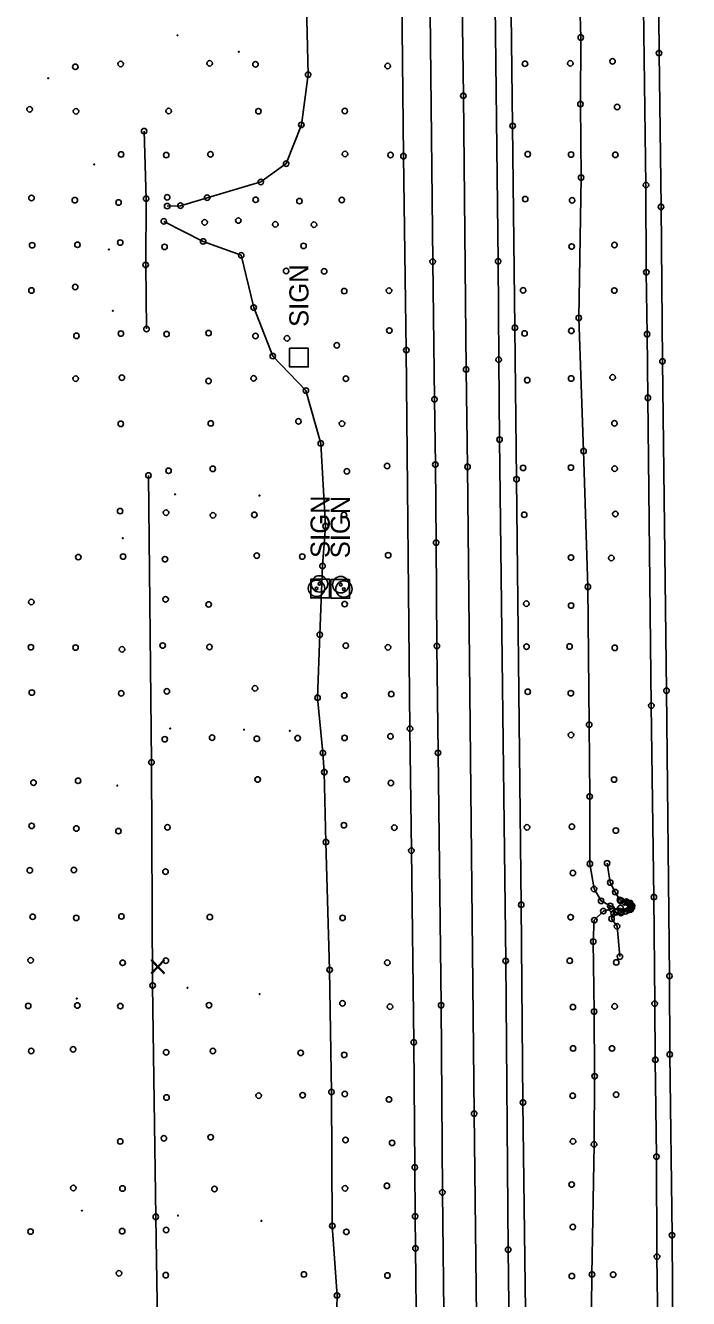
# Model space of a CAD drawing. Extents: x 20503438 to 20508873, y 7964251 to 7984667.
# Drawn here: x 20505218.1 to 20505460.6, y 7983269.7 to 7983735.5 of the extents above; entities that cross this region are included whole.
import ezdxf

# ---------------------------------------------------------------- set-up
doc = ezdxf.new("R2010")
doc.units = 0
for name, color, linetype in [('SurBreakLine', 7, 'Continuous'), ('SurConcreteSlab', 7, 'Continuous'), ('SurControl', 7, 'Continuous'), ('SurDrainageArrowDown', 7, 'Continuous'), ('SurDrainageArrowUp', 7, 'Continuous'), ('SurEdgeRoadPaved', 7, 'Continuous'), ('SurEdgeShoulderPaved', 7, 'Continuous'), ('SurFenceWire', 7, 'Continuous'), ('SurPointsNonDTM', 7, 'Continuous'), ('SurRoadPoints', 7, 'Continuous'), ('SurSurveyPoints', 7, 'Continuous')]:
    doc.layers.add(name, color=color, linetype=linetype)

msp = doc.modelspace()

# ---------------------------------------------------------------- linework, layer by layer
at = {"layer": 'SurBreakLine'}
for points in [[(20505388.09, 7982786.72), (20505387.46, 7982826.69), (20505386.97, 7982893.61), (20505385.8, 7982999.79), (20505385.32, 7983030.07), (20505384.98, 7983076.27), (20505384.47, 7983119.49), (20505384.1, 7983167.57), (20505382.15, 7983337.32), (20505379.76, 7983573.99), (20505379.24, 7983609.63), (20505378.24, 7983709.76), (20505377.29, 7983778.59), (20505376.87, 7983823.71), (20505376.2, 7983914.92), (20505375.66, 7983955.45), (20505374.47, 7984054.03), (20505371.04, 7984409.5), (20505370.34, 7984465.16)], [(20505430.81, 7983428.95), (20505431.94, 7983421.89), (20505433.78, 7983418.39), (20505435.46, 7983415.54), (20505437.89, 7983414.91), (20505439.2, 7983414.35), (20505439.89, 7983413.53), (20505439.86, 7983412.7), (20505439.4, 7983412.02), (20505437.62, 7983411.33), (20505436.03, 7983410.93), (20505435.76, 7983410.73), (20505434.14, 7983411.03), (20505433.19, 7983410.64), (20505432.43, 7983408.64), (20505434.42, 7983405.87), (20505435.48, 7983394.78)]]:
    msp.add_lwpolyline(points, dxfattribs=at)
at = {"layer": 'SurConcreteSlab'}
msp.add_lwpolyline([(20505435.85, 7983415.35), (20505438.25, 7983414.57), (20505439.21, 7983414.26), (20505439.53, 7983413.73), (20505439.61, 7983412.57), (20505439.09, 7983412.1), (20505438.55, 7983411.79), (20505435.96, 7983411), (20505435.9, 7983411.25), (20505438.99, 7983412.12), (20505438.94, 7983414.02), (20505437.2, 7983414.63), (20505435.64, 7983415.19)], dxfattribs=at)
at = {"layer": 'SurControl'}
msp.add_lwpolyline([(20505268.93, 7983393.31), (20505268.67, 7983393.56), (20505266.53, 7983391.34), (20505264.39, 7983393.56), (20505264.13, 7983393.31), (20505266.28, 7983391.08), (20505264.13, 7983388.85), (20505264.39, 7983388.6), (20505266.53, 7983390.82), (20505268.67, 7983388.6), (20505268.93, 7983388.85), (20505266.78, 7983391.08)], close=True, dxfattribs=at)
for centre in [(20505273.7, 7983731.89), (20505296.12, 7983725.88), (20505226.42, 7983716.17), (20505243.27, 7983684.65), (20505248.61, 7983653.5), (20505250.04, 7983631.09), (20505272.81, 7983563.94), (20505303.65, 7983563.47), (20505253.69, 7983547.89), (20505271.04, 7983478.26), (20505298.03, 7983477.81), (20505314.75, 7983477.39), (20505251.69, 7983457.37), (20505236.87, 7983379.43), (20505277.36, 7983383.39), (20505303.75, 7983381.07), (20505238.75, 7983301.84), (20505273.87, 7983300.04), (20505304.38, 7983298.09)]:
    msp.add_circle(centre, 0.15, dxfattribs=at)
at = {"layer": 'SurDrainageArrowDown'}
msp.add_lwpolyline([(20505331.52, 7983247.58), (20505332.03, 7983270.82), (20505330.3, 7983296.26), (20505330, 7983345.23), (20505329.34, 7983389.92), (20505327.98, 7983436.68), (20505327.39, 7983462.27), (20505326.88, 7983469.31), (20505324.92, 7983489.49), (20505325.74, 7983512.6), (20505326.72, 7983537.72), (20505327.84, 7983552.32), (20505326.1, 7983582.56), (20505320.66, 7983601.9), (20505308.53, 7983614.51), (20505301.56, 7983632.27), (20505297, 7983651.4), (20505283.09, 7983656.45), (20505268.69, 7983663.8)], dxfattribs=at)
at = {"layer": 'SurDrainageArrowUp'}
for points in [[(20505269.92, 7983669.38), (20505274.77, 7983669.53), (20505284.53, 7983672.48), (20505304.14, 7983678.22), (20505313.43, 7983684.93), (20505319, 7983699.12), (20505321.46, 7983717.49), (20505321, 7983737.68), (20505321.32, 7983758.43), (20505323.53, 7983782.34), (20505317.99, 7983807.64), (20505321.24, 7983834.42), (20505321.13, 7983884.66), (20505321.58, 7983916.57), (20505320.13, 7983948.66), (20505320.6, 7983976.69), (20505320.82, 7984005.51), (20505319.96, 7984030.22), (20505318.49, 7984055.46), (20505317.7, 7984079.41), (20505317.25, 7984104.99), (20505316.36, 7984122.1)], [(20505431.94, 7983413.35), (20505428.59, 7983415.16), (20505426.01, 7983419.53), (20505424.51, 7983428.73), (20505424.44, 7983453.4), (20505424.24, 7983479.66), (20505423.78, 7983530.09), (20505422.18, 7983579.75), (20505420.43, 7983628.49), (20505421.29, 7983679.84), (20505421.05, 7983706.71), (20505421.16, 7983731.09), (20505419.67, 7983779.95)], [(20505435.69, 7983412.57), (20505432.5, 7983412.27), (20505429.44, 7983411.43), (20505426.11, 7983408.1), (20505425.72, 7983400.28), (20505426.05, 7983374.69), (20505426.24, 7983351.03), (20505426.02, 7983326.08), (20505425.25, 7983278.5), (20505424.77, 7983230.05), (20505424.95, 7983179.92)]]:
    msp.add_lwpolyline(points, dxfattribs=at)
at = {"layer": 'SurEdgeRoadPaved'}
for points in [[(20505403.63, 7982474.93), (20505402.88, 7982536.9), (20505402.67, 7982576.67), (20505401.63, 7982665.51), (20505399.87, 7982796.43), (20505397.64, 7982996.42), (20505397.31, 7983043.62), (20505395.75, 7983196.59), (20505394.62, 7983287.56), (20505393.71, 7983393.22), (20505391.47, 7983583.96), (20505391.16, 7983613.2), (20505390.95, 7983649.19), (20505388.69, 7983846.62), (20505387.86, 7983937.63), (20505387.13, 7984000.04), (20505387.09, 7984002.85), (20505386.65, 7984030.88), (20505382.6, 7984465.04)], [(20505460.57, 7982745.92), (20505460.02, 7982819.87), (20505458.85, 7982918.92), (20505458.72, 7982952.55), (20505457.28, 7983055.18), (20505456.07, 7983138.84), (20505455.85, 7983167.22), (20505455.42, 7983198.13), (20505455.22, 7983224.45), (20505454.85, 7983254.02), (20505454.55, 7983292.83), (20505453.72, 7983358.98), (20505453.59, 7983387.67), (20505452.51, 7983492.09), (20505451.03, 7983612.62), (20505450.51, 7983669.13), (20505449.78, 7983725.38), (20505449.64, 7983752.99)], [(20505376.87, 7982720.03), (20505375.97, 7982814.93), (20505375.18, 7982868.35), (20505374.84, 7982896.8), (20505373.9, 7983003.41), (20505373.63, 7983032.61), (20505373.23, 7983073.5), (20505372.9, 7983110.52), (20505372.72, 7983130.62), (20505372.2, 7983185.46), (20505371.76, 7983214.03), (20505371.18, 7983254.01), (20505370.55, 7983308.55), (20505370.11, 7983376.99), (20505368.96, 7983469.33), (20505368.55, 7983508.46), (20505368.26, 7983546.26), (20505367.99, 7983574.82), (20505367.67, 7983598.7), (20505367.02, 7983649.08), (20505365.92, 7983751.56)]]:
    msp.add_lwpolyline(points, dxfattribs=at)
at = {"layer": 'SurEdgeShoulderPaved'}
for points in [[(20505366.98, 7982718.13), (20505365.41, 7982861.87), (20505365.07, 7982881.72), (20505364.41, 7982928.72), (20505364.19, 7982960.53), (20505363.22, 7983054.03), (20505362.96, 7983074.76), (20505362.61, 7983110.31), (20505362.42, 7983145.46), (20505361.97, 7983183.06), (20505361.41, 7983217.22), (20505361.15, 7983254.72), (20505360.71, 7983288.06), (20505360.6, 7983299.77), (20505360.47, 7983317.66), (20505360.11, 7983363.4), (20505359.23, 7983433.57), (20505358.71, 7983478.18), (20505357.37, 7983616.7), (20505356.33, 7983687.67), (20505355.63, 7983757.41)], [(20505406.44, 7982753), (20505405.66, 7982815.99), (20505404.36, 7982949.58), (20505403.42, 7983021.17), (20505402.75, 7983090.32), (20505402.21, 7983129.29), (20505402.08, 7983165.66), (20505401.47, 7983227.06), (20505400.04, 7983341.4), (20505399.38, 7983413.75), (20505397.66, 7983569.46), (20505397.07, 7983624.87), (20505396.26, 7983698.73), (20505395.49, 7983760.73)], [(20505454.87, 7982799.91), (20505454.43, 7982834.05), (20505454.19, 7982863.65), (20505453.63, 7982922.83), (20505451.09, 7983092.97), (20505450.78, 7983121.42), (20505450.67, 7983149.63), (20505450.35, 7983185.44), (20505449.91, 7983215.31), (20505449.29, 7983259.23), (20505449.04, 7983285.01), (20505448.83, 7983321.6), (20505448.42, 7983357.03), (20505448.19, 7983377.57), (20505447.91, 7983416.56), (20505446.96, 7983486.61), (20505445.72, 7983599.24), (20505445.42, 7983622.54), (20505445.14, 7983645.21), (20505445.01, 7983677.11), (20505444.05, 7983741.95)]]:
    msp.add_lwpolyline(points, dxfattribs=at)
at = {"layer": 'SurFenceWire'}
for points in [[(20505262.37, 7983624.43), (20505262.08, 7983647.88), (20505262.23, 7983672.11), (20505261.49, 7983696.84)], [(20505263.07, 7983570.84), (20505264.2, 7983465.89), (20505264.6, 7983384.22), (20505265.76, 7983299.57), (20505267.13, 7983213.61), (20505277.91, 7983026.79), (20505279.9, 7982903.03), (20505280.94, 7982831.19), (20505284.45, 7982664.16), (20505302.4, 7982645.24), (20505317.11, 7982628.42), (20505340.63, 7982610.34)]]:
    msp.add_lwpolyline(points, dxfattribs=at)
at = {"layer": 'SurPointsNonDTM'}
for centre in [(20505261.49, 7983696.84), (20505262.23, 7983672.11), (20505262.08, 7983647.88), (20505262.37, 7983624.43), (20505263.07, 7983570.84), (20505264.2, 7983465.89), (20505264.6, 7983384.22), (20505265.76, 7983299.57)]:
    msp.add_circle(centre, 1, dxfattribs=at)
at = {"layer": 'SurRoadPoints'}
for points in [[(20505321.53, 7983613.98), (20505321.53, 7983613.98), (20505321.53, 7983617.41), (20505314.67, 7983617.41), (20505314.67, 7983610.55), (20505321.53, 7983610.55), (20505321.53, 7983613.98)], [(20505329.29, 7983529.45), (20505329.29, 7983529.45), (20505329.29, 7983532.88), (20505322.43, 7983532.88), (20505322.43, 7983526.02), (20505329.29, 7983526.02), (20505329.29, 7983529.45)], [(20505336.65, 7983529.32), (20505336.65, 7983529.32), (20505336.65, 7983532.75), (20505329.79, 7983532.75), (20505329.79, 7983525.89), (20505336.65, 7983525.89), (20505336.65, 7983529.32)]]:
    msp.add_lwpolyline(points, dxfattribs=at)
for centre, radius in [((20505325.63, 7983531.17), 3), ((20505333.39, 7983530.88), 3), ((20505324.54, 7983529.51), 3), ((20505324.54, 7983529.51), 0.5), ((20505325.63, 7983531.17), 0.5), ((20505334.55, 7983529.28), 3), ((20505333.39, 7983530.88), 0.5), ((20505334.55, 7983529.28), 0.5)]:
    msp.add_circle(centre, radius, dxfattribs=at)
at = {"layer": 'SurSurveyPoints'}
for centre in [(20505421.16, 7983731.09), (20505449.78, 7983725.38), (20505236.34, 7983720.37), (20505252.92, 7983721.41), (20505285.46, 7983721.62), (20505302.22, 7983721.27), (20505350.55, 7983720.65), (20505400.75, 7983721.47), (20505417.35, 7983721.62), (20505432.8, 7983722.37), (20505321.46, 7983717.49), (20505378.24, 7983709.76), (20505219.65, 7983704.81), (20505236.59, 7983704.08), (20505270.47, 7983704.19), (20505303.31, 7983704.11), (20505334.87, 7983704.17), (20505421.05, 7983706.71), (20505434.47, 7983705.65), (20505319, 7983699.12), (20505396.26, 7983698.73), (20505253.08, 7983688.3), (20505269.59, 7983688.06), (20505285.74, 7983688.33), (20505334.97, 7983688.45), (20505351.62, 7983688.09), (20505356.33, 7983687.67), (20505401.78, 7983688.4), (20505417.63, 7983688.26), (20505433.81, 7983688.16), (20505313.43, 7983684.93), (20505304.14, 7983678.22), (20505421.29, 7983679.84), (20505445.01, 7983677.11), (20505220.32, 7983672.38), (20505236.16, 7983671.56), (20505269.94, 7983672.58), (20505284.53, 7983672.48), (20505302.28, 7983671.7), (20505333.78, 7983671.64), (20505400.86, 7983671.95), (20505418, 7983671.49), (20505252.16, 7983670.71), (20505269.92, 7983669.38), (20505274.77, 7983669.53), (20505318.29, 7983671.21), (20505450.51, 7983669.13), (20505268.69, 7983663.8), (20505283.62, 7983663.47), (20505295.95, 7983664.09), (20505309.47, 7983662.72), (20505323.6, 7983662.59), (20505220.56, 7983655.07), (20505237.12, 7983655.24), (20505252.75, 7983656.06), (20505268.97, 7983654.47), (20505283.09, 7983656.45), (20505319.8, 7983654.85), (20505417.82, 7983654.6), (20505433.49, 7983655.17), (20505297, 7983651.4), (20505367.02, 7983649.08), (20505390.95, 7983649.19), (20505313.41, 7983645.63), (20505327.33, 7983645.52), (20505445.14, 7983645.21), (20505236.3, 7983639.77), (20505220.29, 7983638.52), (20505334.67, 7983638.3), (20505351.06, 7983638.46), (20505400.07, 7983638.57), (20505433.44, 7983638.5), (20505301.56, 7983632.27), (20505397.07, 7983624.87), (20505420.43, 7983628.49), (20505236.76, 7983621.92), (20505253.01, 7983622.77), (20505269.69, 7983622.56), (20505285.05, 7983622.93), (20505302.23, 7983621.86), (20505313.76, 7983620.99), (20505351.15, 7983623.87), (20505400.61, 7983622.8), (20505417.74, 7983623.76), (20505445.42, 7983622.54), (20505331.95, 7983618.47), (20505357.37, 7983616.7), (20505308.53, 7983614.51), (20505391.16, 7983613.2), (20505451.03, 7983612.62), (20505236.47, 7983606.26), (20505253.38, 7983606.64), (20505301.53, 7983606.37), (20505335.28, 7983606.24), (20505379.24, 7983609.63), (20505417.65, 7983606.31), (20505432.83, 7983606.74), (20505285.06, 7983605.38), (20505320.66, 7983601.9), (20505401.58, 7983605.71), (20505367.67, 7983598.7), (20505445.72, 7983599.24), (20505252.95, 7983589.73), (20505285.86, 7983589.88), (20505317.93, 7983590.62), (20505333.84, 7983589.81), (20505433.49, 7983589.89), (20505391.47, 7983583.96), (20505326.1, 7983582.56), (20505422.18, 7983579.75), (20505350.34, 7983574.28), (20505367.99, 7983574.82), (20505379.76, 7983573.99), (20505400.09, 7983573.6), (20505417.55, 7983573.74), (20505270.43, 7983572.54), (20505286.6, 7983573.26), (20505335.64, 7983572.35), (20505397.66, 7983569.46), (20505433.54, 7983573.32), (20505252.72, 7983557.79), (20505269.5, 7983557.23), (20505286.68, 7983556.27), (20505301.78, 7983556.43), (20505334.58, 7983556.43), (20505400.5, 7983556.44), (20505433.83, 7983556.75), (20505327.84, 7983552.32), (20505368.26, 7983546.26), (20505253.81, 7983541.17), (20505302.7, 7983541.5), (20505319.32, 7983541.17), (20505350.74, 7983541.64), (20505237.42, 7983540.97), (20505269.11, 7983540.2), (20505326.72, 7983537.72), (20505417.59, 7983540.81), (20505432.34, 7983540.63), (20505423.78, 7983530.09), (20505220.25, 7983524.53), (20505269.35, 7983525.52), (20505285.08, 7983523.65), (20505334.81, 7983523.77), (20505401.27, 7983523.92), (20505417.63, 7983523.23), (20505268.3, 7983508.61), (20505325.74, 7983512.6), (20505335.24, 7983508.54), (20505368.55, 7983508.46), (20505220.08, 7983507.99), (20505236.42, 7983507.86), (20505253.43, 7983507.2), (20505285.37, 7983508.08), (20505350.67, 7983507.95), (20505401.33, 7983508.21), (20505417.08, 7983508.26), (20505433.61, 7983507.77), (20505220.44, 7983491.4), (20505253.13, 7983491.11), (20505269.81, 7983491.87), (20505302.02, 7983492.94), (20505334.69, 7983490.35), (20505351.86, 7983490.83), (20505401.78, 7983491.69), (20505417.54, 7983491.17), (20505452.51, 7983492.09), (20505324.92, 7983489.49), (20505446.96, 7983486.61), (20505358.71, 7983478.18), (20505417.61, 7983475.89), (20505424.24, 7983479.66), (20505269.06, 7983474.32), (20505286.35, 7983474.92), (20505302.71, 7983474.49), (20505317.66, 7983474.71), (20505334.78, 7983474.81), (20505351.57, 7983475.38), (20505326.88, 7983469.31), (20505368.96, 7983469.33), (20505327.39, 7983462.27), (20505221.04, 7983458.43), (20505237.36, 7983459.12), (20505303.01, 7983459.59), (20505335.55, 7983459.6), (20505351.74, 7983458.3), (20505433.36, 7983459.58), (20505424.44, 7983453.4), (20505220.36, 7983442.62), (20505236.72, 7983441.66), (20505252.11, 7983440.72), (20505270.01, 7983442.07), (20505334.54, 7983442.86), (20505352.97, 7983441.99), (20505401.5, 7983442.11), (20505417.92, 7983442.32), (20505433.99, 7983440.92), (20505327.98, 7983436.68), (20505359.23, 7983433.57), (20505219.71, 7983426.37), (20505235.81, 7983426.46), (20505269.31, 7983425.89), (20505418.3, 7983425.36), (20505424.51, 7983428.73), (20505430.81, 7983428.95), (20505431.94, 7983421.89), (20505426.01, 7983419.53), (20505433.78, 7983418.39), (20505435.46, 7983415.54), (20505435.85, 7983415.35), (20505447.91, 7983416.56), (20505399.38, 7983413.75), (20505428.59, 7983415.16), (20505429.44, 7983411.43), (20505431.94, 7983413.35), (20505432.5, 7983412.27), (20505433.19, 7983410.64), (20505434.14, 7983411.03), (20505435.64, 7983415.19), (20505435.69, 7983412.57), (20505435.76, 7983410.73), (20505435.9, 7983411.25), (20505435.96, 7983411), (20505436.03, 7983410.93), (20505437.2, 7983414.63), (20505437.62, 7983411.33), (20505437.89, 7983414.91), (20505438.25, 7983414.57), (20505438.55, 7983411.79), (20505438.94, 7983414.02), (20505438.99, 7983412.12), (20505439.09, 7983412.1), (20505439.2, 7983414.35), (20505439.21, 7983414.26), (20505439.4, 7983412.02), (20505439.53, 7983413.73), (20505439.61, 7983412.57), (20505439.86, 7983412.7), (20505439.89, 7983413.53), (20505220.72, 7983409.37), (20505236.67, 7983408.94), (20505253.21, 7983409.49), (20505285.53, 7983409.24), (20505334.07, 7983408.95), (20505417.45, 7983409.21), (20505426.11, 7983408.1), (20505432.43, 7983408.64), (20505434.42, 7983405.87), (20505425.72, 7983400.28), (20505219.99, 7983393.44), (20505253.64, 7983392.53), (20505269.45, 7983393.3), (20505350.42, 7983392.56), (20505393.71, 7983393.22), (20505417.16, 7983393.27), (20505434.14, 7983392.64), (20505435.48, 7983394.78), (20505329.34, 7983389.92), (20505453.59, 7983387.67), (20505219.11, 7983376.74), (20505237.07, 7983376.9), (20505252.82, 7983376.67), (20505285.24, 7983377.01), (20505334.04, 7983377.71), (20505351.39, 7983376.47), (20505370.11, 7983376.99), (20505418.29, 7983376.31), (20505426.05, 7983374.69), (20505433.54, 7983376.58), (20505448.19, 7983377.57), (20505220.22, 7983360.24), (20505235.53, 7983360.86), (20505269.56, 7983359.75), (20505286.64, 7983360.24), (20505318.75, 7983359.56), (20505360.11, 7983363.4), (20505418.37, 7983361.19), (20505432.59, 7983361.18), (20505334.66, 7983358.81), (20505448.42, 7983357.03), (20505453.72, 7983358.98), (20505426.24, 7983351.03), (20505269.68, 7983343.24), (20505303.4, 7983343.91), (20505319.49, 7983344.07), (20505330, 7983345.23), (20505334.88, 7983344.52), (20505351.05, 7983342.52), (20505400.04, 7983341.4), (20505418.2, 7983343.88), (20505434.08, 7983344.28), (20505382.15, 7983337.32), (20505252.75, 7983327.15), (20505268.73, 7983328.3), (20505285.83, 7983328.71), (20505335.14, 7983327.7), (20505418.32, 7983327.18), (20505352.18, 7983326.62), (20505426.02, 7983326.08), (20505360.47, 7983317.66), (20505448.83, 7983321.6), (20505235.62, 7983310.14), (20505253.59, 7983309.94), (20505287.21, 7983309.76), (20505334.96, 7983310), (20505350.27, 7983310.92), (20505370.55, 7983308.55), (20505417.85, 7983311.37), (20505360.6, 7983299.77), (20505219.96, 7983294.17), (20505253.47, 7983294.33), (20505269.53, 7983294.77), (20505330.3, 7983296.26), (20505418.25, 7983295.86), (20505335.44, 7983294.07), (20505454.55, 7983292.83), (20505360.71, 7983288.06), (20505394.62, 7983287.56), (20505449.04, 7983285.01), (20505252.29, 7983278.92), (20505269.42, 7983278.23), (20505319.91, 7983278.49), (20505350.47, 7983278.11), (20505417.9, 7983277.89), (20505425.25, 7983278.5), (20505433.01, 7983278.43), (20505332.03, 7983270.82)]:
    msp.add_circle(centre, 1, dxfattribs=at)

# ---------------------------------------------------------------- texts
at = {"layer": 'SurRoadPoints'}
for p in [(20505321.6, 7983625.19), (20505329.36, 7983540.66), (20505336.72, 7983540.53)]:
    msp.add_text('SIGN', height=6.995, rotation=90, dxfattribs=at).set_placement(p)

doc.saveas('drawing.dxf')
